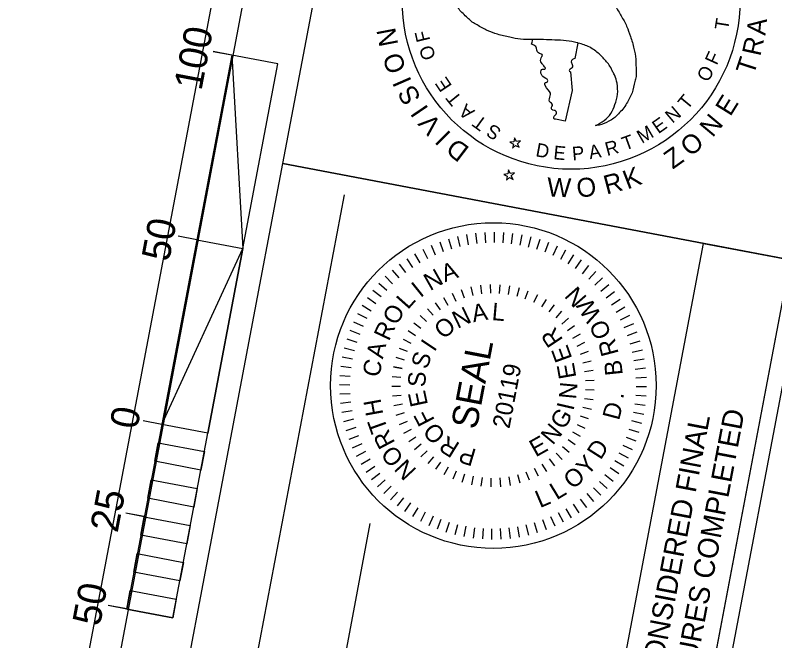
# Model space of a CAD drawing. Extents: x 1615680 to 1617075, y 898420 to 901376.
# Drawn here: x 1616769.3 to 1616971.6, y 900493.9 to 900660.3 of the extents above; entities that cross this region are included whole.
import ezdxf

# ---------------------------------------------------------------- set-up
doc = ezdxf.new("R2010")
doc.units = 0
for name, color, linetype in [('Default', 7, 'Continuous'), ('DEV BORDER CELL', 7, 'Continuous'), ('DEV DOT SWIRL SEAL CELL', 7, 'Continuous'), ('Scratch_Level_0', 7, 'Continuous'), ('Sheet Clip Boundary CELL', 7, 'Continuous'), ('Sheet Data Field CELL', 7, 'Continuous'), ('Sheet Sticker Exception Certification CELL', 7, 'Continuous'), ('Sheet Title CELL', 7, 'Continuous'), ('Text', 7, 'Continuous')]:
    doc.layers.add(name, color=color, linetype=linetype)

msp = doc.modelspace()

# ---------------------------------------------------------------- linework, layer by layer
at = {"layer": 'Default'}
for p, q in [((1616889.49, 900601.99), (1616889.97, 900599.25)), ((1616891.93, 900602.35), (1616892.24, 900599.58)), ((1616894.39, 900602.55), (1616894.54, 900599.77)), ((1616896.86, 900602.61), (1616896.84, 900599.82)), ((1616899.33, 900602.51), (1616899.14, 900599.74)), ((1616901.78, 900602.27), (1616901.43, 900599.51)), ((1616904.22, 900601.88), (1616903.7, 900599.15)), ((1616882.35, 900600.06), (1616883.32, 900597.45)), ((1616884.69, 900600.85), (1616885.5, 900598.18)), ((1616887.07, 900601.49), (1616887.72, 900598.78)), ((1616906.64, 900601.35), (1616905.95, 900598.65)), ((1616909.01, 900600.67), (1616908.16, 900598.01)), ((1616911.34, 900599.85), (1616910.33, 900597.25)), ((1616877.83, 900598.07), (1616879.11, 900595.59)), ((1616880.06, 900599.13), (1616881.18, 900596.58)), ((1616913.61, 900598.89), (1616912.45, 900596.35)), ((1616875.67, 900596.87), (1616877.1, 900594.47)), ((1616915.82, 900597.79), (1616914.51, 900595.33)), ((1616917.96, 900596.56), (1616916.5, 900594.18)), ((1616871.59, 900594.09), (1616873.29, 900591.89)), ((1616873.59, 900595.54), (1616875.15, 900593.24)), ((1616920.02, 900595.2), (1616918.43, 900592.92)), ((1616869.68, 900592.52), (1616871.51, 900590.43)), ((1616922.01, 900593.73), (1616920.27, 900591.54)), ((1616923.89, 900592.13), (1616922.03, 900590.06)), ((1616867.87, 900590.85), (1616869.82, 900588.86)), ((1616925.68, 900590.42), (1616923.69, 900588.47)), ((1616866.17, 900589.06), (1616868.24, 900587.2)), ((1616890.62, 900588.01), (1616891.14, 900585.75)), ((1616893.19, 900588.46), (1616893.48, 900586.16)), ((1616895.78, 900588.66), (1616895.85, 900586.34)), ((1616898.39, 900588.61), (1616898.23, 900586.3)), ((1616900.97, 900588.31), (1616900.59, 900586.02)), ((1616903.52, 900587.76), (1616902.92, 900585.52)), ((1616927.35, 900588.62), (1616925.26, 900586.78)), ((1616864.57, 900587.18), (1616866.75, 900585.44)), ((1616885.68, 900586.38), (1616886.63, 900584.26)), ((1616888.11, 900587.31), (1616888.85, 900585.11)), ((1616905.1, 900584.82), (1616905.91, 900587)), ((1616908.39, 900585.94), (1616907.37, 900583.86)), ((1616928.92, 900586.7), (1616926.72, 900585)), ((1616863.1, 900585.2), (1616865.37, 900583.6)), ((1616881.15, 900583.83), (1616882.48, 900581.92)), ((1616883.36, 900585.21), (1616884.49, 900583.19)), ((1616910.67, 900584.69), (1616909.45, 900582.71)), ((1616930.37, 900584.71), (1616928.07, 900583.14)), ((1616861.73, 900583.14), (1616864.11, 900581.67)), ((1616879.09, 900582.24), (1616880.6, 900580.47)), ((1616912.81, 900583.22), (1616911.41, 900581.37)), ((1616931.69, 900582.62), (1616929.3, 900581.2)), ((1616860.51, 900581), (1616862.97, 900579.68)), ((1616877.19, 900580.46), (1616878.87, 900578.85)), ((1616914.81, 900581.55), (1616913.24, 900579.84)), ((1616916.64, 900579.69), (1616914.91, 900578.14)), ((1616932.89, 900580.46), (1616930.42, 900579.19)), ((1616859.41, 900578.78), (1616861.94, 900577.62)), ((1616875.48, 900578.5), (1616877.29, 900577.06)), ((1616918.28, 900577.67), (1616916.41, 900576.3)), ((1616933.96, 900578.24), (1616931.41, 900577.11)), ((1616858.45, 900576.51), (1616861.05, 900575.5)), ((1616873.96, 900576.39), (1616875.91, 900575.13)), ((1616934.89, 900575.95), (1616932.27, 900574.98)), ((1616857.63, 900574.18), (1616860.28, 900573.33)), ((1616872.65, 900574.14), (1616874.71, 900573.07)), ((1616919.72, 900575.5), (1616917.72, 900574.31)), ((1616935.68, 900573.61), (1616933.01, 900572.8)), ((1616856.95, 900571.81), (1616859.65, 900571.12)), ((1616871.56, 900571.77), (1616873.72, 900570.91)), ((1616920.94, 900573.2), (1616918.84, 900572.21)), ((1616921.93, 900570.8), (1616919.74, 900570.01)), ((1616936.32, 900571.22), (1616933.61, 900570.58)), ((1616856.41, 900569.4), (1616859.15, 900568.87)), ((1616870.71, 900569.31), (1616872.94, 900568.66)), ((1616922.69, 900568.3), (1616920.43, 900567.74)), ((1616936.82, 900568.81), (1616934.08, 900568.32)), ((1616856.02, 900566.96), (1616858.78, 900566.6)), ((1616870.1, 900566.78), (1616872.38, 900566.35)), ((1616872.38, 900566.35), (1616870.1, 900566.78)), ((1616923.2, 900565.75), (1616920.9, 900565.4)), ((1616937.18, 900566.37), (1616934.4, 900566.05)), ((1616855.78, 900564.5), (1616858.56, 900564.31)), ((1616869.74, 900564.2), (1616872.05, 900563.99)), ((1616937.38, 900563.9), (1616934.6, 900563.76)), ((1616855.69, 900562.03), (1616858.47, 900562.01)), ((1616869.62, 900561.61), (1616871.94, 900561.61)), ((1616923.46, 900563.16), (1616921.14, 900563.04)), ((1616937.44, 900561.43), (1616934.65, 900561.46)), ((1616855.74, 900559.57), (1616858.52, 900559.71)), ((1616923.48, 900560.56), (1616921.16, 900560.66)), ((1616855.95, 900557.1), (1616858.72, 900557.42)), ((1616869.76, 900559.01), (1616872.07, 900559.24)), ((1616923.24, 900557.97), (1616920.94, 900558.29)), ((1616937.34, 900558.97), (1616934.57, 900559.16)), ((1616870.15, 900556.43), (1616872.43, 900556.89)), ((1616922.75, 900555.41), (1616920.49, 900555.95)), ((1616937.1, 900556.51), (1616934.34, 900556.87)), ((1616856.3, 900554.66), (1616859.05, 900555.14)), ((1616870.78, 900553.91), (1616873, 900554.58)), ((1616922.02, 900552.91), (1616919.82, 900553.67)), ((1616936.71, 900554.07), (1616933.98, 900554.59)), ((1616856.81, 900552.24), (1616859.51, 900552.89)), ((1616871.66, 900551.45), (1616873.81, 900552.34)), ((1616918.93, 900551.45), (1616921.04, 900550.48)), ((1616936.18, 900551.66), (1616933.48, 900552.35)), ((1616857.45, 900549.86), (1616860.12, 900550.67)), ((1616872.77, 900549.1), (1616874.82, 900550.19)), ((1616919.85, 900548.19), (1616917.84, 900549.36)), ((1616935.49, 900549.29), (1616932.84, 900550.13)), ((1616858.24, 900547.52), (1616860.85, 900548.49)), ((1616874.1, 900546.86), (1616876.04, 900548.15)), ((1616918.43, 900546), (1616916.54, 900547.36)), ((1616934.68, 900546.96), (1616932.08, 900547.96)), ((1616859.17, 900545.23), (1616861.71, 900546.36)), ((1616875.64, 900544.76), (1616877.44, 900546.23)), ((1616916.81, 900543.96), (1616915.06, 900545.5)), ((1616933.71, 900544.69), (1616931.18, 900545.84)), ((1616860.23, 900543.01), (1616862.71, 900544.28)), ((1616877.37, 900542.82), (1616879.03, 900544.45)), ((1616915, 900542.09), (1616913.41, 900543.79)), ((1616932.62, 900542.47), (1616930.15, 900543.78)), ((1616861.43, 900540.84), (1616863.82, 900542.27)), ((1616879.29, 900541.06), (1616880.78, 900542.84)), ((1616881.36, 900539.49), (1616882.67, 900541.41)), ((1616913.02, 900540.4), (1616911.6, 900542.24)), ((1616931.39, 900540.33), (1616929.01, 900541.79)), ((1616862.75, 900538.76), (1616865.06, 900540.33)), ((1616883.58, 900538.13), (1616884.7, 900540.16)), ((1616908.62, 900537.64), (1616907.58, 900539.72)), ((1616910.88, 900538.92), (1616909.65, 900540.88)), ((1616930.03, 900538.27), (1616927.75, 900539.87)), ((1616864.2, 900536.76), (1616866.41, 900538.46)), ((1616885.92, 900536.98), (1616886.84, 900539.12)), ((1616888.36, 900536.07), (1616889.06, 900538.28)), ((1616890.87, 900535.4), (1616891.37, 900537.67)), ((1616893.44, 900534.97), (1616893.71, 900537.28)), ((1616898.64, 900534.87), (1616898.46, 900537.19)), ((1616901.23, 900535.2), (1616900.82, 900537.49)), ((1616903.76, 900535.78), (1616903.14, 900538.01)), ((1616906.23, 900536.59), (1616905.4, 900538.76)), ((1616928.55, 900536.29), (1616926.37, 900538.02)), ((1616865.77, 900534.85), (1616867.87, 900536.68)), ((1616896.04, 900534.8), (1616896.08, 900537.12)), ((1616926.96, 900534.4), (1616924.89, 900536.27)), ((1616867.45, 900533.04), (1616869.43, 900535)), ((1616869.23, 900531.34), (1616871.1, 900533.41)), ((1616925.25, 900532.62), (1616923.3, 900534.6)), ((1616871.12, 900529.74), (1616872.85, 900531.92)), ((1616921.53, 900529.37), (1616919.83, 900531.58)), ((1616923.44, 900530.94), (1616921.61, 900533.04)), ((1616873.1, 900528.27), (1616874.69, 900530.55)), ((1616875.16, 900526.91), (1616876.62, 900529.28)), ((1616919.53, 900527.93), (1616917.97, 900530.23)), ((1616877.3, 900525.68), (1616878.61, 900528.14)), ((1616879.52, 900524.58), (1616880.67, 900527.11)), ((1616915.29, 900525.4), (1616914.02, 900527.88)), ((1616917.45, 900526.6), (1616916.03, 900528.99)), ((1616881.79, 900523.62), (1616882.79, 900526.22)), ((1616884.12, 900522.8), (1616884.96, 900525.45)), ((1616908.44, 900522.62), (1616907.63, 900525.29)), ((1616910.78, 900523.41), (1616909.81, 900526.02)), ((1616913.07, 900524.34), (1616911.94, 900526.88)), ((1616886.49, 900522.12), (1616887.17, 900524.82)), ((1616888.9, 900521.58), (1616889.42, 900524.32)), ((1616891.34, 900521.19), (1616891.7, 900523.96)), ((1616893.8, 900520.95), (1616893.99, 900523.73)), ((1616896.26, 900520.86), (1616896.28, 900523.64)), ((1616898.73, 900520.91), (1616898.59, 900523.7)), ((1616901.19, 900521.12), (1616900.88, 900523.89)), ((1616903.63, 900521.47), (1616903.15, 900524.22)), ((1616906.05, 900521.98), (1616905.41, 900524.69))]:
    msp.add_line(p, q, dxfattribs=at)
at = {"layer": 'DEV BORDER CELL'}
for p, q in [((1616863.68, 900616.49), (1616975.68, 900595.23)), ((1616829.71, 900468.75), (1616857, 900612.52)), ((1616849, 900446.64), (1616863.88, 900525.03))]:
    msp.add_line(p, q, dxfattribs=at)
for points in [[(1616014.55, 901139.21), (1615734.74, 899665.53), (1616766.32, 899469.67), (1617046.12, 900943.35)], [(1616840.59, 900620.87), (1616861.86, 900732.87), (1616996.95, 900707.23), (1616975.68, 900595.22)], [(1616803.28, 900424.35), (1616840.59, 900620.87), (1616975.68, 900595.22), (1616938.37, 900398.7)]]:
    msp.add_lwpolyline(points, close=True, dxfattribs=at)
msp.add_circle((1616896.65, 900561.78), 43.34, dxfattribs=at)
at = {"layer": 'DEV DOT SWIRL SEAL CELL'}
for p, q in [((1616918.41, 900648.8), (1616919.23, 900652.93)), ((1616917.17, 900645.27), (1616917.66, 900640.28)), ((1616917.66, 900640.28), (1616915.79, 900632.1)), ((1616915.79, 900632.1), (1616913.19, 900632.68)), ((1616902.1, 900626.67), (1616901.05, 900626.51)), ((1616901.05, 900626.51), (1616901.98, 900626)), ((1616902.31, 900627.74), (1616902.1, 900626.67)), ((1616902.77, 900626.75), (1616902.31, 900627.74)), ((1616903.86, 900626.87), (1616902.77, 900626.75)), ((1616903.06, 900626.12), (1616903.86, 900626.87)), ((1616903.54, 900625.18), (1616903.06, 900626.12)), ((1616901.98, 900626), (1616901.78, 900624.94)), ((1616901.78, 900624.94), (1616902.57, 900625.69)), ((1616902.57, 900625.69), (1616903.54, 900625.18)), ((1616900.47, 900618.15), (1616899.42, 900617.98)), ((1616900.67, 900619.21), (1616900.47, 900618.15)), ((1616901.14, 900618.23), (1616900.67, 900619.21)), ((1616901.14, 900618.23), (1616900.68, 900619.22)), ((1616902.23, 900618.35), (1616901.14, 900618.23)), ((1616902.23, 900618.35), (1616901.14, 900618.23)), ((1616901.43, 900617.6), (1616902.23, 900618.35)), ((1616901.43, 900617.6), (1616902.23, 900618.35)), ((1616899.42, 900617.98), (1616900.35, 900617.48)), ((1616900.35, 900617.48), (1616900.14, 900616.42)), ((1616900.14, 900616.42), (1616900.94, 900617.16)), ((1616900.94, 900617.16), (1616901.91, 900616.65)), ((1616901.91, 900616.65), (1616901.43, 900617.6))]:
    msp.add_line(p, q, dxfattribs=at)
msp.add_arc((1616681.63, 900713.24), 233.19, 344.9279, 345.2256, dxfattribs=at)
for points in [[(1616942.02, 900686.2), (1616939.76, 900687.51), (1616937.22, 900688.12), (1616934.64, 900687.9), (1616931.95, 900687.13), (1616929.47, 900685.55), (1616927.98, 900684.03), (1616927.45, 900683.12), (1616926.46, 900681.67), (1616925.87, 900680.28), (1616925.1, 900677.53), (1616924.79, 900674.45), (1616925.36, 900671.25), (1616925.42, 900670.99), (1616926.44, 900668.18), (1616927.8, 900665.43), (1616929.16, 900662.79), (1616930.68, 900660.13), (1616932.13, 900657.42), (1616933.14, 900654.69), (1616934.09, 900651.45), (1616934.55, 900648.6), (1616934.65, 900645.52), (1616934.64, 900643.99), (1616934.34, 900642.71), (1616933.59, 900639.66), (1616932.13, 900636.85), (1616931.1, 900635.29), (1616929.97, 900634.12), (1616929.8, 900633.9), (1616927.41, 900632.12), (1616924.81, 900631.11), (1616923.83, 900630.99)], [(1616923.83, 900630.99), (1616926.14, 900632.33), (1616927.91, 900634.21), (1616929.01, 900636.54), (1616929.7, 900639.28), (1616929.57, 900642.22), (1616928.98, 900644.28), (1616928.5, 900645.19), (1616927.68, 900646.76), (1616926.81, 900647.94), (1616924.8, 900650.02), (1616922.29, 900651.8), (1616919.26, 900652.93), (1616919, 900653), (1616916.04, 900653.54), (1616912.98, 900653.71), (1616910.03, 900653.83), (1616906.95, 900653.87), (1616903.91, 900653.96), (1616901.02, 900654.45), (1616897.76, 900655.26), (1616895.03, 900656.27), (1616892.3, 900657.74), (1616891.02, 900658.51), (1616890.04, 900659.4), (1616887.76, 900661.61), (1616886.08, 900664.25), (1616885.25, 900665.94), (1616884.78, 900667.48), (1616884.69, 900667.74), (1616884.32, 900670.71), (1616884.74, 900673.47), (1616885.15, 900674.35)], [(1616913.19, 900632.68), (1616912.93, 900632.64), (1616912.74, 900633.14), (1616913.47, 900634.27), (1616913.06, 900634.98), (1616912.52, 900635.05), (1616912.09, 900635.65), (1616912.42, 900636.45), (1616911.61, 900637.38), (1616911.55, 900638.11), (1616911.83, 900639.58), (1616910.41, 900641.66), (1616910.44, 900642.4), (1616910.95, 900642.51), (1616911.12, 900642.94), (1616909.82, 900643.99), (1616909.66, 900644.22), (1616909.36, 900645.66), (1616909.71, 900645.97), (1616910.37, 900645.96), (1616910.51, 900646.13), (1616910.29, 900646.63), (1616909.63, 900647.39), (1616909.26, 900648.61), (1616909.67, 900649.86), (1616908.65, 900650.28), (1616907.94, 900651.97), (1616907.39, 900652.39), (1616906.79, 900652.59)], [(1616918.41, 900648.8), (1616917.71, 900648.59), (1616917.39, 900647.96), (1616917.69, 900646.95), (1616917.54, 900646.29), (1616916.84, 900645.65), (1616917.17, 900645.27)]]:
    msp.add_spline(points, degree=3, dxfattribs=at)
at = {"layer": 'Scratch_Level_0'}
msp.add_lwpolyline([(1616054.34, 901080.76), (1615793.19, 899705.33), (1616726.52, 899528.12), (1616890.46, 900391.55), (1616774.26, 900413.61), (1616871.48, 900925.61)], close=True, dxfattribs=at)
at = {"layer": 'Sheet Clip Boundary CELL'}
msp.add_lwpolyline([(1616176.29, 901060.7), (1616913.78, 900900.04), (1616896.28, 900812.91), (1616872.94, 900688.21), (1616835.87, 900695.21), (1616753.94, 900262.18), (1616898.09, 900233.43), (1616663.91, 899565.73), (1616252.62, 899604.04), (1615894.68, 899796.73), (1615981.58, 900932.46), (1616145.94, 900899.57)], close=True, dxfattribs=at)
at = {"layer": 'Sheet Data Field CELL'}
for p, q in [((1616826.99, 900649.7), (1616822.06, 900650.64)), ((1616817.65, 900600.58), (1616812.75, 900601.51)), ((1616803.68, 900526.9), (1616798.77, 900527.83)), ((1616799.01, 900502.34), (1616794.11, 900503.27))]:
    msp.add_line(p, q, dxfattribs=at)
at = {"layer": 'Sheet Sticker Exception Certification CELL'}
for p, q in [((1616915.28, 900403.08), (1616952.59, 900599.61)), ((1616952.6, 900599.61), (1616975.69, 900595.22)), ((1616975.68, 900595.22), (1616938.37, 900398.7))]:
    msp.add_line(p, q, dxfattribs=at)
at = {"layer": 'Sheet Title CELL'}
for p, q in [((1616826.98, 900649.69), (1616822.07, 900650.62)), ((1616826.98, 900649.69), (1616799.02, 900502.32)), ((1616839.28, 900647.36), (1616826.98, 900649.69)), ((1616811.3, 900499.99), (1616839.28, 900647.36)), ((1616817.66, 900600.57), (1616812.76, 900601.5)), ((1616817.66, 900600.57), (1616829.94, 900598.24)), ((1616808.35, 900551.44), (1616803.44, 900552.37)), ((1616805.54, 900536.71), (1616817.82, 900534.38)), ((1616803.69, 900526.88), (1616798.76, 900527.82)), ((1616799.02, 900502.32), (1616794.12, 900503.25)), ((1616799.02, 900502.32), (1616811.3, 900499.99))]:
    msp.add_line(p, q, dxfattribs=at)
for points in [[(1616826.98, 900649.69), (1616829.94, 900598.24), (1616839.28, 900647.36)], [(1616808.35, 900551.44), (1616829.94, 900598.24), (1616820.63, 900549.11)], [(1616806.47, 900541.62), (1616807.41, 900546.53), (1616819.7, 900544.2), (1616818.75, 900539.29)], [(1616804.62, 900531.79), (1616805.54, 900536.71), (1616817.82, 900534.38), (1616816.89, 900529.46)], [(1616802.76, 900521.97), (1616803.69, 900526.88), (1616815.96, 900524.55), (1616815.03, 900519.64)], [(1616800.88, 900512.15), (1616801.82, 900517.06), (1616814.11, 900514.73), (1616813.18, 900509.83)], [(1616799.02, 900502.32), (1616799.95, 900507.23), (1616812.23, 900504.9), (1616811.3, 900499.99)]]:
    msp.add_lwpolyline(points, close=True, dxfattribs=at)
at = {"layer": 'Text'}
msp.add_circle((1616917.34, 900664.32), 44.97, dxfattribs=at)

# ---------------------------------------------------------------- texts
at = {"layer": 'Default'}
for s, height, rotation, p in [('A', 4.64, 19.7134, (1616883.74, 900589.24)), ('N', 4.64, 29.481, (1616879.8, 900586.88)), ('I', 4.64, 38.7754, (1616877.22, 900585)), ('N', 4.64, 131.4034, (1616921.77, 900585.19)), ('L', 4.64, 48.3509, (1616873.87, 900581.83)), ('L', 4.64, 355.067, (1616896.11, 900579.23)), ('W', 4.64, 122.5208, (1616925.62, 900580.49)), ('O', 4.64, 61.4872, (1616870.95, 900577.58)), ('N', 4.64, 25.6595, (1616887.11, 900576.83)), ('A', 4.64, 10.3632, (1616891.32, 900578.61)), ('O', 4.64, 40.9557, (1616883.39, 900573.9)), ('R', 4.64, 64.544, (1616868.8, 900573.42)), ('O', 4.64, 113.6381, (1616928.19, 900575.35)), ('R', 4.64, 123.7612, (1616915.36, 900573.97)), ('I', 4.64, 56.252, (1616880.91, 900570.56)), ('R', 4.64, 104.8155, (1616930.05, 900570.31)), ('A', 4.64, 76.5533, (1616867.21, 900568.72)), ('SEAL', 6.965, 79.1963, (1616892.17, 900549.87)), ('E', 4.64, 109.9902, (1616917.71, 900569.02)), ('S', 4.64, 71.5482, (1616879, 900565.9)), ('C', 4.64, 76.5533, (1616866.16, 900563.75)), ('E', 4.64, 100.0043, (1616918.76, 900563.97)), ('B', 4.64, 95.813, (1616931.11, 900564.65)), ('20119', 4.64, 79.1963, (1616900.91, 900550.14)), ('S', 4.64, 86.8445, (1616878.51, 900561.28)), ('N', 4.64, 84.6122, (1616918.68, 900558.01)), ('E', 4.64, 102.1407, (1616879.26, 900556.7)), ('H', 4.64, 100.264, (1616867.36, 900554.13)), ('.', 4.64, 83.0287, (1616931.23, 900558.08)), ('G', 4.64, 58.8877, (1616915.44, 900549.79)), ('I', 4.64, 76.9825, (1616917.93, 900554.94)), ('D', 4.64, 75.2863, (1616930.09, 900552.34)), ('F', 4.64, 117.437, (1616881.15, 900552.56)), ('T', 4.64, 109.6959, (1616868.65, 900550.08)), ('O', 4.64, 132.7332, (1616884.24, 900548.83)), ('N', 4.64, 50.1215, (1616912.45, 900545.74)), ('R', 4.64, 117.8569, (1616870.61, 900546.53)), ('R', 4.64, 148.0295, (1616887.99, 900546.25)), ('E', 4.64, 29.2664, (1616907.92, 900542.64)), ('O', 4.64, 130.9136, (1616873.05, 900542.64)), ('D', 4.64, 57.491, (1616925.2, 900541.79)), ('P', 4.64, 163.3257, (1616892.38, 900544.69)), ('Y', 4.64, 48.5185, (1616921.72, 900537.53)), ('N', 4.64, 132.8731, (1616876.4, 900539.29)), ('O', 4.64, 39.8459, (1616917.75, 900533.99)), ('L', 4.64, 31.2032, (1616913.5, 900531.22)), ('L', 4.64, 23.1314, (1616909.05, 900529.14))]:
    msp.add_text(s, height=height, rotation=rotation, dxfattribs=at).set_placement(p)
at = {"layer": 'DEV DOT SWIRL SEAL CELL'}
for s, height, rotation, p in [('T', 3.63, 80.9269, (1616959.13, 900656.22)), ('N', 5.04, 100.8354, (1616871.34, 900652.55)), ('F', 3.63, 103.5063, (1616879.87, 900653.68)), ('O', 3.63, 108.5844, (1616881.39, 900649.11)), ('F', 3.63, 65.6926, (1616956.13, 900646.85)), ('O', 5.04, 109.3428, (1616873.51, 900645.92)), ('O', 3.63, 60.6146, (1616953.76, 900642.29)), ('I', 5.04, 113.6302, (1616874.97, 900642.72)), ('E', 3.63, 123.8186, (1616885.75, 900641.55)), ('S', 5.04, 119.8342, (1616877.51, 900638.3)), ('T', 3.63, 128.8967, (1616888.47, 900638.12)), ('T', 3.63, 50.4584, (1616948.28, 900634.98)), ('I', 5.04, 124.1215, (1616879.53, 900635.42)), ('A', 3.63, 139.0529, (1616891.9, 900634.86)), ('N', 3.63, 40.3022, (1616944.31, 900631.41)), ('V', 5.04, 130.83, (1616883.1, 900631.23)), ('T', 3.63, 144.1309, (1616895.27, 900632.25)), ('E', 3.63, 35.2241, (1616940.57, 900628.64)), ('S', 3.63, 149.209, (1616899.04, 900629.92)), ('M', 3.63, 30.146, (1616936.19, 900626.07)), ('I', 5.04, 135.1173, (1616885.64, 900628.79)), ('T', 3.63, 19.9899, (1616931.68, 900624.26)), ('D', 5.04, 142.7084, (1616890.54, 900624.96)), ('D', 3.63, 349.5214, (1616907.73, 900622.83)), ('R', 3.63, 14.9118, (1616926.93, 900622.84)), ('E', 3.63, 354.5995, (1616912.53, 900622.04)), ('P', 3.63, 4.7556, (1616917.75, 900621.66)), ('A', 3.63, 9.8337, (1616922.36, 900622.01))]:
    msp.add_text(s, height=height, rotation=rotation, dxfattribs=at).set_placement(p)
at = {"layer": 'Sheet Sticker Exception Certification CELL'}
for s, p in [('UNLESS ALL SIGNATURES COMPLETED', (1616937.07, 900415.23)), ('DOCUMENT NOT CONSIDERED FINAL', (1616929.37, 900421.85))]:
    msp.add_text(s, height=5.5, rotation=79.2494, dxfattribs=at).set_placement(p)
at = {"layer": 'Sheet Title CELL'}
for s, p in [('100', (1616818.91, 900640.06)), ('50', (1616810.27, 900594.53)), ('0', (1616801.8, 900549.89)), ('25', (1616796.58, 900522.4)), ('50', (1616791.85, 900497.5))]:
    msp.add_text(s, height=7.5, rotation=79.2541, dxfattribs=at).set_placement(p)
at = {"layer": 'Text'}
for s, rotation, p in [('A', 84.0528, (1616969.07, 900654.81)), ('R', 77.815, (1616967.73, 900649.24)), ('T', 71.9442, (1616965.92, 900644.17)), ('E', 58.201, (1616959.74, 900633.2)), ('N', 50.212, (1616955.01, 900627.61)), ('O', 41.7727, (1616949.21, 900622.48)), ('Z', 35.4181, (1616944.38, 900619.21)), ('K', 21.0412, (1616932.34, 900613.91)), ('R', 14.8034, (1616926.77, 900612.58)), ('W', 357.3994, (1616910.86, 900612.13)), ('O', 6.3641, (1616919.07, 900611.76))]:
    msp.add_text(s, height=5.04, rotation=rotation, dxfattribs=at).set_placement(p)

doc.saveas('drawing.dxf')
